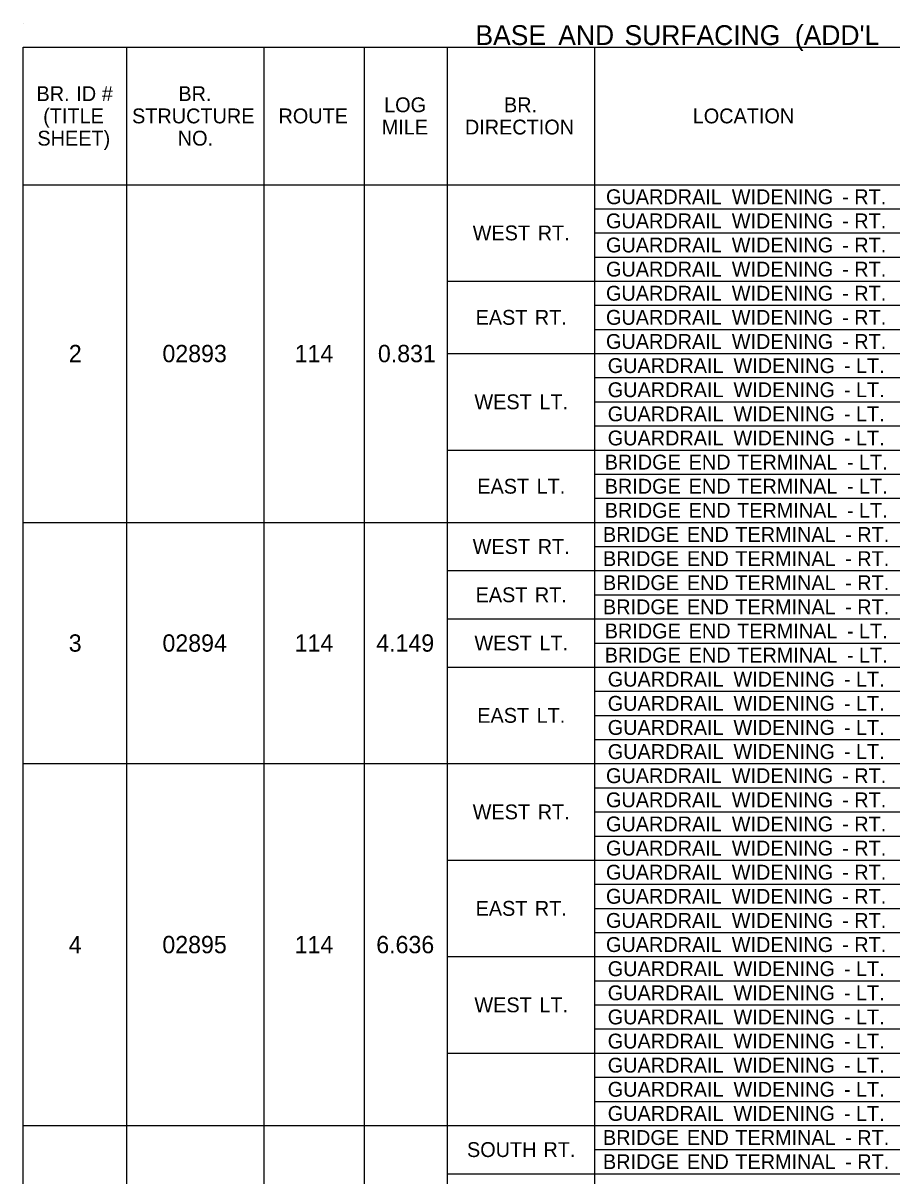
# Model space of a CAD drawing. Extents: x 542596 to 1930787, y -1948294 to 596640.
# Drawn here: x 552219.7 to 552570.9, y -1946585.9 to -1946119.9 of the extents above; entities that cross this region are included whole.
import ezdxf

# ---------------------------------------------------------------- set-up
doc = ezdxf.new("R2010")
doc.units = 0
doc.layers.add('Default', color=7, linetype='Continuous')

msp = doc.modelspace()

# ---------------------------------------------------------------- linework, layer by layer
at = {"layer": 'Default'}
for p, q in [((552219.67, -1946119.94), (552219.67, -1946119.94)), ((552219.67, -1946129.69), (552968.47, -1946129.69)), ((552219.67, -1946838.51), (552219.67, -1946129.69)), ((552261.6, -1946321.76), (552261.6, -1946129.69)), ((552261.6, -1946838.51), (552261.6, -1946129.69)), ((552317.17, -1946838.51), (552317.17, -1946129.69)), ((552357.64, -1946838.51), (552357.64, -1946129.69)), ((552391.27, -1946838.51), (552391.27, -1946129.69)), ((552450.75, -1946848.26), (552450.75, -1946129.69)), ((552219.67, -1946185.26), (552968.47, -1946185.26)), ((552450.75, -1946195.01), (552968.47, -1946195.01)), ((552450.75, -1946204.76), (552968.47, -1946204.76)), ((552450.75, -1946214.51), (552968.47, -1946214.51)), ((552391.27, -1946224.26), (552968.47, -1946224.26)), ((552391.27, -1946224.26), (552450.75, -1946224.26)), ((552450.75, -1946234.01), (552968.47, -1946234.01)), ((552450.75, -1946243.76), (552968.47, -1946243.76)), ((552391.27, -1946253.51), (552450.75, -1946253.51)), ((552450.75, -1946253.51), (552968.47, -1946253.51)), ((552450.75, -1946263.26), (552968.47, -1946263.26)), ((552450.75, -1946273.01), (552968.47, -1946273.01)), ((552450.75, -1946282.76), (552968.47, -1946282.76)), ((552391.27, -1946292.51), (552968.47, -1946292.51)), ((552391.27, -1946292.51), (552450.75, -1946292.51)), ((552450.75, -1946302.26), (552968.47, -1946302.26)), ((552450.75, -1946312.01), (552968.47, -1946312.01)), ((552219.67, -1946321.76), (552968.47, -1946321.76)), ((552450.75, -1946321.76), (552968.47, -1946321.76)), ((552450.75, -1946331.51), (552918.75, -1946331.51)), ((552391.27, -1946341.26), (552450.75, -1946341.26)), ((552450.75, -1946341.26), (552968.47, -1946341.26)), ((552450.75, -1946351.01), (552968.47, -1946351.01)), ((552391.27, -1946360.76), (552450.75, -1946360.76)), ((552450.75, -1946360.76), (552968.47, -1946360.76)), ((552450.75, -1946370.51), (552968.47, -1946370.51)), ((552391.27, -1946380.26), (552450.75, -1946380.26)), ((552450.75, -1946380.26), (552968.47, -1946380.26)), ((552450.75, -1946390.01), (552968.47, -1946390.01)), ((552450.75, -1946399.76), (552715.95, -1946399.76)), ((552450.75, -1946409.51), (552715.95, -1946409.51)), ((552219.67, -1946419.26), (552968.47, -1946419.26)), ((552450.75, -1946429.01), (552715.95, -1946429.01)), ((552450.75, -1946438.76), (552715.95, -1946438.76)), ((552450.75, -1946448.51), (552968.47, -1946448.51)), ((552391.27, -1946458.26), (552450.75, -1946458.26)), ((552450.75, -1946458.26), (552968.47, -1946458.26)), ((552450.75, -1946468.01), (552968.47, -1946468.01)), ((552450.75, -1946477.76), (552968.47, -1946477.76)), ((552450.75, -1946487.51), (552968.47, -1946487.51)), ((552391.27, -1946497.26), (552968.47, -1946497.26)), ((552391.27, -1946497.26), (552450.75, -1946497.26)), ((552450.75, -1946507.01), (552968.47, -1946507.01)), ((552450.75, -1946516.76), (552968.47, -1946516.76)), ((552450.75, -1946526.51), (552968.47, -1946526.51)), ((552391.27, -1946536.26), (552968.47, -1946536.26)), ((552450.75, -1946546.01), (552968.47, -1946546.01)), ((552450.75, -1946555.76), (552968.47, -1946555.76)), ((552219.67, -1946565.51), (552391.27, -1946565.51)), ((552219.67, -1946565.51), (552357.64, -1946565.51)), ((552357.64, -1946565.51), (552968.47, -1946565.51)), ((552450.75, -1946575.26), (552968.47, -1946575.26)), ((552391.27, -1946585.01), (552450.75, -1946585.01)), ((552450.75, -1946585.01), (552968.47, -1946585.01))]:
    msp.add_line(p, q, dxfattribs=at)

# ---------------------------------------------------------------- texts
for s, height, p in [('BASE', 8, (552402.54, -1946128.81)), (' AND', 8, (552433.05, -1946128.81)), (' SURFACING', 8, (552459.82, -1946128.81)), (" (ADD'L", 8, (552528.69, -1946128.81)), ('BR.', 6, (552225.11, -1946151.47)), (' ID', 6, (552238.97, -1946151.47)), (' #', 6, (552249.27, -1946151.47)), ('BR.', 6, (552282.46, -1946151.47)), ('LOG', 6, (552365.63, -1946155.97)), ('BR.', 6, (552414.08, -1946155.97)), ('(TITLE', 6, (552227.81, -1946160.47)), ('STRUCTURE', 6, (552263.74, -1946160.47)), ('ROUTE', 6, (552322.94, -1946160.47)), ('LOCATION', 6, (552490.38, -1946160.47)), ('MILE', 6, (552364.65, -1946164.97)), ('DIRECTION', 6, (552398.29, -1946164.97)), ('SHEET)', 6, (552225.48, -1946169.47)), ('NO.', 6, (552282.22, -1946169.47)), ('GUARDRAIL', 6, (552455.32, -1946193.14)), (' WIDENING', 6, (552503.94, -1946193.14)), (' RT.', 6, (552553.44, -1946193.14)), (' -', 6, (552548.58, -1946193.14)), ('GUARDRAIL', 6, (552455.32, -1946202.89)), (' WIDENING', 6, (552503.94, -1946202.89)), (' RT.', 6, (552553.44, -1946202.89)), ('WEST', 6, (552401.44, -1946207.76)), (' RT.', 6, (552425.49, -1946207.76)), (' -', 6, (552548.58, -1946202.89)), ('GUARDRAIL', 6, (552455.32, -1946212.64)), (' WIDENING', 6, (552503.94, -1946212.64)), (' RT.', 6, (552553.44, -1946212.64)), (' -', 6, (552548.58, -1946212.64)), ('GUARDRAIL', 6, (552455.32, -1946222.39)), (' WIDENING', 6, (552503.94, -1946222.39)), (' RT.', 6, (552553.44, -1946222.39)), (' -', 6, (552548.58, -1946222.39)), ('GUARDRAIL', 6, (552455.32, -1946232.14)), (' WIDENING', 6, (552503.94, -1946232.14)), (' RT.', 6, (552553.44, -1946232.14)), (' -', 6, (552548.58, -1946232.14)), ('EAST', 6, (552402.6, -1946241.89)), (' RT.', 6, (552424.33, -1946241.89)), ('GUARDRAIL', 6, (552455.32, -1946241.89)), (' WIDENING', 6, (552503.94, -1946241.89)), (' -', 6, (552548.58, -1946241.89)), (' RT.', 6, (552553.44, -1946241.89)), ('GUARDRAIL', 6, (552455.32, -1946251.64)), (' WIDENING', 6, (552503.94, -1946251.64)), (' -', 6, (552548.58, -1946251.64)), (' RT.', 6, (552553.44, -1946251.64)), ('2', 7, (552238.18, -1946257.01)), ('02893', 7, (552276.02, -1946257.01)), ('114', 7, (552329.49, -1946257.01)), ('0.831', 7, (552363.12, -1946257.01)), ('GUARDRAIL', 6, (552456.02, -1946261.39)), (' WIDENING', 6, (552504.63, -1946261.39)), (' -', 6, (552549.28, -1946261.39)), (' LT.', 6, (552554.14, -1946261.39)), ('GUARDRAIL', 6, (552456.02, -1946271.14)), (' WIDENING', 6, (552504.63, -1946271.14)), (' LT.', 6, (552554.14, -1946271.14)), ('WEST', 6, (552402.13, -1946276.01)), (' LT.', 6, (552426.18, -1946276.01)), (' -', 6, (552549.28, -1946271.14)), ('GUARDRAIL', 6, (552456.02, -1946280.89)), (' WIDENING', 6, (552504.63, -1946280.89)), (' LT.', 6, (552554.14, -1946280.89)), (' -', 6, (552549.28, -1946280.89)), ('GUARDRAIL', 6, (552456.02, -1946290.64)), (' WIDENING', 6, (552504.63, -1946290.64)), (' LT.', 6, (552554.14, -1946290.64)), (' -', 6, (552549.28, -1946290.64)), ('BRIDGE', 6, (552454.8, -1946300.39)), (' END', 6, (552486.5, -1946300.39)), (' TERMINAL', 6, (552506.08, -1946300.39)), (' LT.', 6, (552555.36, -1946300.39)), (' -', 6, (552550.5, -1946300.39)), ('EAST', 6, (552403.29, -1946310.14)), (' LT.', 6, (552425.03, -1946310.14)), ('BRIDGE', 6, (552454.8, -1946310.14)), (' END', 6, (552486.5, -1946310.14)), (' TERMINAL', 6, (552506.08, -1946310.14)), (' LT.', 6, (552555.36, -1946310.14)), (' -', 6, (552550.5, -1946310.14)), ('BRIDGE', 6, (552454.8, -1946319.89)), (' END', 6, (552486.5, -1946319.89)), (' TERMINAL', 6, (552506.08, -1946319.89)), (' LT.', 6, (552555.36, -1946319.89)), (' -', 6, (552550.5, -1946319.89)), ('BRIDGE', 6, (552454.1, -1946329.64)), (' END', 6, (552485.8, -1946329.64)), (' TERMINAL', 6, (552505.38, -1946329.64)), (' RT.', 6, (552554.66, -1946329.64)), ('WEST', 6, (552401.44, -1946334.51)), (' RT.', 6, (552425.49, -1946334.51)), (' -', 6, (552549.8, -1946329.64)), ('BRIDGE', 6, (552454.1, -1946339.39)), (' END', 6, (552485.8, -1946339.39)), (' TERMINAL', 6, (552505.38, -1946339.39)), (' RT.', 6, (552554.66, -1946339.39)), (' -', 6, (552549.8, -1946339.39)), ('BRIDGE', 6, (552454.1, -1946349.14)), (' END', 6, (552485.8, -1946349.14)), (' TERMINAL', 6, (552505.38, -1946349.14)), (' -', 6, (552549.8, -1946349.14)), (' RT.', 6, (552554.66, -1946349.14)), ('EAST', 6, (552402.6, -1946354.01)), (' RT.', 6, (552424.33, -1946354.01)), ('BRIDGE', 6, (552454.1, -1946358.89)), (' END', 6, (552485.8, -1946358.89)), (' TERMINAL', 6, (552505.38, -1946358.89)), (' -', 6, (552549.8, -1946358.89)), (' RT.', 6, (552554.66, -1946358.89)), ('BRIDGE', 6, (552454.8, -1946368.64)), (' END', 6, (552486.5, -1946368.64)), (' TERMINAL', 6, (552506.08, -1946368.64)), (' -', 6, (552550.5, -1946368.64)), (' LT.', 6, (552555.36, -1946368.64)), ('3', 7, (552238.14, -1946374.01)), ('02894', 7, (552276.03, -1946374.01)), ('114', 7, (552329.49, -1946374.01)), ('4.149', 7, (552362.44, -1946374.01)), ('WEST', 6, (552402.13, -1946373.51)), (' LT.', 6, (552426.18, -1946373.51)), ('BRIDGE', 6, (552454.8, -1946378.39)), (' END', 6, (552486.5, -1946378.39)), (' TERMINAL', 6, (552506.08, -1946378.39)), (' LT.', 6, (552555.36, -1946378.39)), (' -', 6, (552550.5, -1946378.39)), ('GUARDRAIL', 6, (552456.02, -1946388.14)), (' WIDENING', 6, (552504.63, -1946388.14)), (' LT.', 6, (552554.14, -1946388.14)), (' -', 6, (552549.28, -1946388.14)), ('GUARDRAIL', 6, (552456.02, -1946397.89)), (' WIDENING', 6, (552504.63, -1946397.89)), (' LT.', 6, (552554.14, -1946397.89)), ('EAST', 6, (552403.29, -1946402.76)), (' LT.', 6, (552425.03, -1946402.76)), (' -', 6, (552549.28, -1946397.89)), ('GUARDRAIL', 6, (552456.02, -1946407.64)), (' WIDENING', 6, (552504.63, -1946407.64)), (' LT.', 6, (552554.14, -1946407.64)), (' -', 6, (552549.28, -1946407.64)), ('GUARDRAIL', 6, (552456.02, -1946417.39)), (' WIDENING', 6, (552504.63, -1946417.39)), (' LT.', 6, (552554.14, -1946417.39)), (' -', 6, (552549.28, -1946417.39)), ('GUARDRAIL', 6, (552455.32, -1946427.14)), (' WIDENING', 6, (552503.94, -1946427.14)), (' RT.', 6, (552553.44, -1946427.14)), (' -', 6, (552548.58, -1946427.14)), ('GUARDRAIL', 6, (552455.32, -1946436.89)), (' WIDENING', 6, (552503.94, -1946436.89)), (' RT.', 6, (552553.44, -1946436.89)), ('WEST', 6, (552401.44, -1946441.76)), (' RT.', 6, (552425.49, -1946441.76)), (' -', 6, (552548.58, -1946436.89)), ('GUARDRAIL', 6, (552455.32, -1946446.64)), (' WIDENING', 6, (552503.94, -1946446.64)), (' RT.', 6, (552553.44, -1946446.64)), (' -', 6, (552548.58, -1946446.64)), ('GUARDRAIL', 6, (552455.32, -1946456.39)), (' WIDENING', 6, (552503.94, -1946456.39)), (' -', 6, (552548.58, -1946456.39)), (' RT.', 6, (552553.44, -1946456.39)), ('GUARDRAIL', 6, (552455.32, -1946466.14)), (' WIDENING', 6, (552503.94, -1946466.14)), (' -', 6, (552548.58, -1946466.14)), (' RT.', 6, (552553.44, -1946466.14)), ('GUARDRAIL', 6, (552455.32, -1946475.89)), (' WIDENING', 6, (552503.94, -1946475.89)), (' -', 6, (552548.58, -1946475.89)), (' RT.', 6, (552553.44, -1946475.89)), ('EAST', 6, (552402.6, -1946480.76)), (' RT.', 6, (552424.33, -1946480.76)), ('GUARDRAIL', 6, (552455.32, -1946485.64)), (' WIDENING', 6, (552503.94, -1946485.64)), (' RT.', 6, (552553.44, -1946485.64)), (' -', 6, (552548.58, -1946485.64)), ('4', 7, (552238.16, -1946495.89)), ('02895', 7, (552275.99, -1946495.89)), ('114', 7, (552329.49, -1946495.89)), ('6.636', 7, (552362.45, -1946495.89)), ('GUARDRAIL', 6, (552455.32, -1946495.39)), (' WIDENING', 6, (552503.94, -1946495.39)), (' RT.', 6, (552553.44, -1946495.39)), (' -', 6, (552548.58, -1946495.39)), ('GUARDRAIL', 6, (552456.02, -1946505.14)), (' WIDENING', 6, (552504.63, -1946505.14)), (' LT.', 6, (552554.14, -1946505.14)), (' -', 6, (552549.28, -1946505.14)), ('GUARDRAIL', 6, (552456.02, -1946514.89)), (' WIDENING', 6, (552504.63, -1946514.89)), (' LT.', 6, (552554.14, -1946514.89)), ('WEST', 6, (552402.13, -1946519.76)), (' LT.', 6, (552426.18, -1946519.76)), (' -', 6, (552549.28, -1946514.89)), ('GUARDRAIL', 6, (552456.02, -1946524.64)), (' WIDENING', 6, (552504.63, -1946524.64)), (' LT.', 6, (552554.14, -1946524.64)), (' -', 6, (552549.28, -1946524.64)), ('GUARDRAIL', 6, (552456.02, -1946534.39)), (' WIDENING', 6, (552504.63, -1946534.39)), (' LT.', 6, (552554.14, -1946534.39)), (' -', 6, (552549.28, -1946534.39)), ('GUARDRAIL', 6, (552456.02, -1946544.14)), (' WIDENING', 6, (552504.63, -1946544.14)), (' LT.', 6, (552554.14, -1946544.14)), (' -', 6, (552549.28, -1946544.14)), ('GUARDRAIL', 6, (552456.02, -1946553.89)), (' WIDENING', 6, (552504.63, -1946553.89)), (' -', 6, (552549.28, -1946553.89)), (' LT.', 6, (552554.14, -1946553.89)), ('GUARDRAIL', 6, (552456.02, -1946563.64)), (' WIDENING', 6, (552504.63, -1946563.64)), (' -', 6, (552549.28, -1946563.64)), (' LT.', 6, (552554.14, -1946563.64)), ('BRIDGE', 6, (552454.1, -1946573.39)), (' END', 6, (552485.8, -1946573.39)), (' TERMINAL', 6, (552505.38, -1946573.39)), (' -', 6, (552549.8, -1946573.39)), (' RT.', 6, (552554.66, -1946573.39)), ('SOUTH', 6, (552399.13, -1946578.26)), (' RT.', 6, (552427.8, -1946578.26)), ('BRIDGE', 6, (552454.1, -1946583.14)), (' END', 6, (552485.8, -1946583.14)), (' TERMINAL', 6, (552505.38, -1946583.14)), (' RT.', 6, (552554.66, -1946583.14)), (' -', 6, (552549.8, -1946583.14))]:
    msp.add_text(s, height=height, dxfattribs=at).set_placement(p)

doc.saveas('drawing.dxf')
